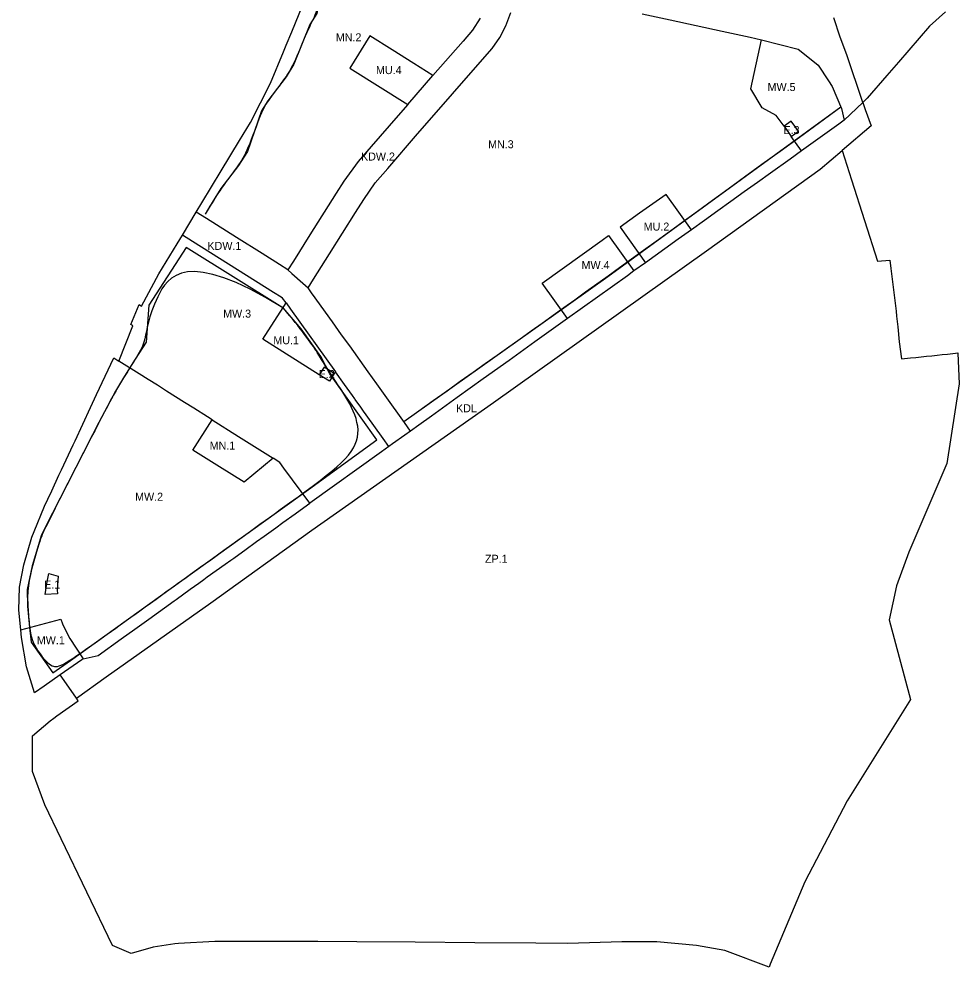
# Model space of a CAD drawing. Extents: x 7421649 to 7422798, y 5542040 to 5543137.
# Drawn here: x 7421743 to 7422272, y 5542040 to 5542573 of the extents above; entities that cross this region are included whole.
import ezdxf

# ---------------------------------------------------------------- set-up
doc = ezdxf.new("R2010")
doc.units = 0
for name, color, linetype in [('linie_rozgraniczajace', 7, 'Continuous'), ('linie_zabudowy_nieprzekraczalne', 7, 'Continuous'), ('oznaczenia_przeznaczen', 7, 'Continuous')]:
    doc.layers.add(name, color=color, linetype=linetype)

msp = doc.modelspace()

# ---------------------------------------------------------------- linework, layer by layer
at = {"layer": 'linie_rozgraniczajace'}
for p, q in [((7421896.4, 5542565.61), (7421904.65, 5542585.63)), ((7422016.73, 5542568.81), (7422019.53, 5542576.39)), ((7422093.43, 5542575.67), (7422109.11, 5542572.26)), ((7422263.95, 5542576.81), (7422254.88, 5542568.62)), ((7422002.25, 5542573.28), (7421997.98, 5542566.51)), ((7422013.26, 5542562.28), (7422016.73, 5542568.81)), ((7422109.11, 5542572.26), (7422123.76, 5542569.07)), ((7422123.76, 5542569.07), (7422138.4, 5542565.87)), ((7422204.6, 5542562.53), (7422201.15, 5542573.32)), ((7421893.27, 5542558.01), (7421896.4, 5542565.61)), ((7421997.98, 5542566.51), (7421992.72, 5542560.37)), ((7422138.4, 5542565.87), (7422154.08, 5542562.47)), ((7422254.88, 5542568.62), (7422237.48, 5542548.49)), ((7421940.34, 5542563.19), (7421928.98, 5542545.12)), ((7421952.79, 5542555.37), (7421940.34, 5542563.19)), ((7421992.72, 5542560.37), (7421975.77, 5542540.92)), ((7422008.97, 5542556.24), (7422013.26, 5542562.28)), ((7422154.08, 5542562.47), (7422160.44, 5542561.08)), ((7422154.45, 5542533.49), (7422160.44, 5542561.08)), ((7422160.44, 5542561.08), (7422181.03, 5542555.82)), ((7422208.35, 5542552.69), (7422204.6, 5542562.53)), ((7421884.37, 5542536.75), (7421891.76, 5542554.35)), ((7421891.76, 5542554.35), (7421893.27, 5542558.01)), ((7421965.02, 5542547.68), (7421952.79, 5542555.37)), ((7422003.6, 5542550.01), (7422008.97, 5542556.24)), ((7422181.03, 5542555.82), (7422188.38, 5542550.04)), ((7421975.77, 5542540.92), (7421965.02, 5542547.68)), ((7421986.73, 5542530.65), (7422003.6, 5542550.01)), ((7422188.38, 5542550.04), (7422192.4, 5542546.88)), ((7422217.47, 5542525.82), (7422208.35, 5542552.69)), ((7422237.48, 5542548.49), (7422230.94, 5542540.92)), ((7421928.98, 5542545.12), (7421961.58, 5542524.63)), ((7422192.4, 5542546.88), (7422198.16, 5542537.92)), ((7421961.58, 5542524.63), (7421975.77, 5542540.92)), ((7422198.16, 5542537.92), (7422200.12, 5542534.87)), ((7422230.94, 5542540.92), (7422219.96, 5542528.19)), ((7421873.19, 5542514.65), (7421884.37, 5542536.75)), ((7422160.86, 5542522.75), (7422154.45, 5542533.49)), ((7422200.12, 5542534.87), (7422205.51, 5542522.37)), ((7421972.53, 5542514.38), (7421986.73, 5542530.65)), ((7422219.96, 5542528.19), (7422217.47, 5542525.82)), ((7421961.58, 5542524.63), (7421956.26, 5542518.53)), ((7422168.78, 5542518.58), (7422160.86, 5542522.75)), ((7422205.51, 5542522.37), (7422207.02, 5542515.84)), ((7422217.47, 5542525.82), (7422207.02, 5542515.84)), ((7422217.47, 5542525.82), (7422218.27, 5542523.48)), ((7422218.27, 5542523.48), (7422218.77, 5542521.9)), ((7422218.77, 5542521.9), (7422222.04, 5542512.78)), ((7421956.26, 5542518.53), (7421941.06, 5542501.06)), ((7422173.15, 5542512.48), (7422168.78, 5542518.58)), ((7422207.02, 5542515.84), (7422203.97, 5542513.66)), ((7421869.03, 5542507.75), (7421873.19, 5542514.65)), ((7421967.13, 5542508.17), (7421972.53, 5542514.38)), ((7422177.21, 5542515.39), (7422173.15, 5542512.48)), ((7422173.15, 5542512.48), (7422177.22, 5542506.79)), ((7422181.29, 5542509.7), (7422177.21, 5542515.39)), ((7422203.97, 5542513.66), (7422183.04, 5542498.66)), ((7422222.04, 5542512.78), (7422205.75, 5542498.85)), ((7421866.99, 5542504.37), (7421869.03, 5542507.75)), ((7421950.29, 5542488.69), (7421967.13, 5542508.17)), ((7422177.22, 5542506.79), (7422181.29, 5542509.7)), ((7422183.04, 5542498.66), (7422177.22, 5542506.79)), ((7421856.74, 5542487.42), (7421866.99, 5542504.37)), ((7421941.06, 5542501.06), (7421933.67, 5542492.56)), ((7422183.04, 5542498.66), (7422176.54, 5542494)), ((7422193.42, 5542488.31), (7422205.75, 5542498.85)), ((7422205.75, 5542498.85), (7422211, 5542482.38)), ((7421933.67, 5542492.56), (7421925.67, 5542481.65)), ((7422176.54, 5542494), (7422165.58, 5542486.15)), ((7421845.84, 5542469.4), (7421856.74, 5542487.42)), ((7421943.29, 5542480.6), (7421950.29, 5542488.69)), ((7422129.51, 5542442.53), (7422193.42, 5542488.31)), ((7422165.58, 5542486.15), (7422158.16, 5542480.84)), ((7421925.67, 5542481.65), (7421921.39, 5542474.89)), ((7421936.89, 5542471.35), (7421943.29, 5542480.6)), ((7422158.16, 5542480.84), (7422150.74, 5542475.52)), ((7422211, 5542482.38), (7422225.61, 5542436.56)), ((7421921.39, 5542474.89), (7421906.57, 5542451.43)), ((7422106.78, 5542474.18), (7422099.36, 5542468.86)), ((7422121.05, 5542454.26), (7422106.78, 5542474.18)), ((7422150.74, 5542475.52), (7422143.31, 5542470.21)), ((7421842.66, 5542464.14), (7421845.84, 5542469.4)), ((7421932.28, 5542464.04), (7421936.89, 5542471.35)), ((7422099.36, 5542468.86), (7422091.93, 5542463.55)), ((7422143.31, 5542470.21), (7422135.89, 5542464.89)), ((7421834.91, 5542451.3), (7421842.66, 5542464.14)), ((7421848.4, 5542460.53), (7421842.66, 5542464.14)), ((7421917.62, 5542440.85), (7421932.28, 5542464.04)), ((7422091.93, 5542463.55), (7422080.98, 5542455.7)), ((7422135.89, 5542464.89), (7422128.47, 5542459.58)), ((7421853.97, 5542457.03), (7421848.4, 5542460.53)), ((7421865.27, 5542449.92), (7421853.97, 5542457.03)), ((7422128.47, 5542459.58), (7422121.05, 5542454.26)), ((7422080.98, 5542455.7), (7422095.24, 5542435.78)), ((7422121.05, 5542454.26), (7422113.62, 5542448.95)), ((7421821.7, 5542429.48), (7421831.92, 5542446.35)), ((7421831.92, 5542446.35), (7421834.91, 5542451.3)), ((7421840.54, 5542447.76), (7421834.91, 5542451.3)), ((7421886.12, 5542419.11), (7421840.54, 5542447.76)), ((7421879.66, 5542440.88), (7421865.27, 5542449.92)), ((7421906.57, 5542451.43), (7421897.26, 5542436.71)), ((7422037.07, 5542424.26), (7422070.93, 5542448.5)), ((7422070.93, 5542448.5), (7422074.47, 5542451.04)), ((7422074.47, 5542451.04), (7422088.73, 5542431.12)), ((7422113.62, 5542448.95), (7422106.2, 5542443.63)), ((7421889.5, 5542434.7), (7421879.66, 5542440.88)), ((7422009.88, 5542357.13), (7422129.51, 5542442.53)), ((7422106.2, 5542443.63), (7422095.24, 5542435.78)), ((7421897.26, 5542436.71), (7421894.14, 5542431.78)), ((7421908.56, 5542426.52), (7421917.62, 5542440.85)), ((7422095.24, 5542435.78), (7422088.73, 5542431.12)), ((7422225.61, 5542436.56), (7422232.58, 5542437.19)), ((7422232.58, 5542437.19), (7422233.27, 5542432.57)), ((7421894.14, 5542431.78), (7421889.5, 5542434.7)), ((7421894.14, 5542431.78), (7421896.39, 5542429.79)), ((7422088.73, 5542431.12), (7422085.05, 5542428.48)), ((7422233.27, 5542432.57), (7422233.63, 5542429.57)), ((7421811.94, 5542411.41), (7421821.7, 5542429.48)), ((7421896.39, 5542429.79), (7421902.63, 5542424.27)), ((7421905.52, 5542421.72), (7421908.56, 5542426.52)), ((7422085.05, 5542428.48), (7422051.34, 5542404.34)), ((7422233.63, 5542429.57), (7422233.98, 5542426.57)), ((7422233.98, 5542426.57), (7422234.33, 5542423.58)), ((7421902.63, 5542424.27), (7421905.52, 5542421.72)), ((7421907.91, 5542418.38), (7421905.52, 5542421.72)), ((7422051.34, 5542404.34), (7422037.07, 5542424.26)), ((7422234.33, 5542423.58), (7422234.68, 5542420.59)), ((7422234.68, 5542420.59), (7422235.03, 5542417.6)), ((7421890.42, 5542416.4), (7421886.12, 5542419.11)), ((7421891.25, 5542415.88), (7421890.42, 5542416.4)), ((7421893.15, 5542413.23), (7421891.25, 5542415.88)), ((7421908.09, 5542418.13), (7421907.91, 5542418.38)), ((7421919.29, 5542402.49), (7421908.09, 5542418.13)), ((7422235.03, 5542417.6), (7422235.38, 5542414.61)), ((7422235.38, 5542414.61), (7422235.74, 5542411.62)), ((7421805.81, 5542401.09), (7421810.65, 5542412.21)), ((7421810.65, 5542412.21), (7421811.94, 5542411.41)), ((7421880.12, 5542392.76), (7421893.15, 5542413.23)), ((7421893.15, 5542413.23), (7421895.75, 5542409.61)), ((7421895.75, 5542409.61), (7421920.88, 5542374.53)), ((7422235.74, 5542411.62), (7422236.09, 5542408.63)), ((7422051.34, 5542404.34), (7422044.83, 5542399.68)), ((7422236.09, 5542408.63), (7422236.44, 5542405.65)), ((7422236.44, 5542405.65), (7422236.79, 5542402.66)), ((7421799.17, 5542380.46), (7421807.1, 5542400.28)), ((7421807.1, 5542400.28), (7421805.81, 5542401.09)), ((7421924.41, 5542395.34), (7421919.29, 5542402.49)), ((7422044.83, 5542399.68), (7422033.08, 5542391.27)), ((7422236.79, 5542402.66), (7422237.14, 5542399.67)), ((7422237.14, 5542399.67), (7422237.89, 5542391.37)), ((7421928.95, 5542388.99), (7421924.41, 5542395.34)), ((7421911.86, 5542372.8), (7421880.12, 5542392.76)), ((7421939.38, 5542374.42), (7421928.95, 5542388.99)), ((7422033.08, 5542391.27), (7422018.54, 5542380.85)), ((7422237.89, 5542391.37), (7422239.16, 5542381.72)), ((7421786.63, 5542361.7), (7421796.27, 5542382.28)), ((7421796.27, 5542382.28), (7421799.17, 5542380.46)), ((7422244.19, 5542382.24), (7422247.18, 5542382.56)), ((7422247.18, 5542382.56), (7422250.17, 5542382.87)), ((7422250.17, 5542382.87), (7422253.16, 5542383.19)), ((7422253.16, 5542383.19), (7422256.15, 5542383.51)), ((7422256.15, 5542383.51), (7422259.14, 5542383.82)), ((7422259.14, 5542383.82), (7422262.13, 5542384.13)), ((7422262.13, 5542384.13), (7422265.12, 5542384.45)), ((7422265.12, 5542384.45), (7422268.11, 5542384.76)), ((7422268.11, 5542384.76), (7422271.1, 5542385.07)), ((7422271.1, 5542385.07), (7422270.83, 5542384.9)), ((7422270.83, 5542384.9), (7422271.53, 5542367.62)), ((7421810.5, 5542373.33), (7421799.17, 5542380.46)), ((7421914.58, 5542377.13), (7421911.86, 5542372.8)), ((7421920.25, 5542373.56), (7421914.58, 5542377.13)), ((7422018.54, 5542380.85), (7422003.98, 5542370.43)), ((7422239.16, 5542381.72), (7422244.19, 5542382.24)), ((7421815.65, 5542370.1), (7421810.5, 5542373.33)), ((7421917.54, 5542369.24), (7421911.86, 5542372.8)), ((7421920.25, 5542373.56), (7421917.54, 5542369.24)), ((7421920.88, 5542374.53), (7421920.25, 5542373.56)), ((7421926.01, 5542367.38), (7421920.88, 5542374.53)), ((7421944.12, 5542367.78), (7421939.38, 5542374.42)), ((7421820.81, 5542366.87), (7421815.65, 5542370.1)), ((7421825.88, 5542363.66), (7421820.81, 5542366.87)), ((7421930.53, 5542361.07), (7421926.01, 5542367.38)), ((7421944.24, 5542367.62), (7421944.12, 5542367.78)), ((7421948.9, 5542361.12), (7421944.24, 5542367.62)), ((7422003.98, 5542370.43), (7421989.43, 5542360)), ((7422271.53, 5542367.62), (7422264.64, 5542322.9)), ((7421783.24, 5542354.35), (7421786.63, 5542361.7)), ((7421830.96, 5542360.46), (7421825.88, 5542363.66)), ((7421931.75, 5542359.34), (7421930.53, 5542361.07)), ((7421959.75, 5542345.97), (7421948.9, 5542361.12)), ((7421836.11, 5542357.23), (7421830.96, 5542360.46)), ((7421841.27, 5542354), (7421836.11, 5542357.23)), ((7421907.61, 5542285.51), (7422009.88, 5542357.13)), ((7421932.06, 5542358.89), (7421931.75, 5542359.34)), ((7421935.11, 5542354.64), (7421932.06, 5542358.89)), ((7421989.43, 5542360), (7421974.88, 5542349.58)), ((7421774.58, 5542335.75), (7421783.24, 5542354.35)), ((7421848.99, 5542349.14), (7421841.27, 5542354)), ((7421935.58, 5542353.98), (7421935.11, 5542354.64)), ((7421936.72, 5542352.39), (7421935.58, 5542353.98)), ((7421938.17, 5542350.36), (7421936.72, 5542352.39)), ((7421947.68, 5542337.08), (7421938.17, 5542350.36)), ((7421840.79, 5542330.47), (7421851.53, 5542347.54)), ((7421851.53, 5542347.54), (7421848.99, 5542349.14)), ((7421851.53, 5542347.54), (7421866.37, 5542338.2)), ((7421963.17, 5542341.2), (7421959.75, 5542345.97)), ((7421974.88, 5542349.58), (7421967.79, 5542344.51)), ((7421963.17, 5542341.2), (7421959.94, 5542338.89)), ((7421967.79, 5542344.51), (7421963.17, 5542341.2)), ((7421773.52, 5542333.5), (7421774.58, 5542335.75)), ((7421866.37, 5542338.2), (7421885.97, 5542325.89)), ((7421950.98, 5542332.47), (7421947.68, 5542337.08)), ((7421959.94, 5542338.89), (7421953.02, 5542333.93)), ((7421766.83, 5542319.3), (7421773.52, 5542333.5)), ((7421855.74, 5542321.09), (7421840.79, 5542330.47)), ((7421946.73, 5542329.42), (7421906.51, 5542300.62)), ((7421950.98, 5542332.47), (7421946.73, 5542329.42)), ((7421953.02, 5542333.93), (7421950.98, 5542332.47)), ((7421885.97, 5542325.89), (7421869.53, 5542312.42)), ((7421889.63, 5542323.58), (7421885.97, 5542325.89)), ((7421765.42, 5542316.31), (7421766.83, 5542319.3)), ((7421869.53, 5542312.42), (7421855.74, 5542321.09)), ((7421892, 5542320.36), (7421889.63, 5542323.58)), ((7421906.51, 5542300.62), (7421892, 5542320.36)), ((7422264.64, 5542322.9), (7422243.24, 5542273.2)), ((7421761.42, 5542307.66), (7421765.42, 5542316.31)), ((7421759.15, 5542302.83), (7421761.42, 5542307.66)), ((7421757.37, 5542299.03), (7421759.15, 5542302.83)), ((7421751.47, 5542284.76), (7421757.37, 5542299.03)), ((7421899.07, 5542295.23), (7421906.51, 5542300.62)), ((7421891.41, 5542289.72), (7421898.36, 5542294.72)), ((7421898.36, 5542294.72), (7421899.07, 5542295.23)), ((7421880.87, 5542282.15), (7421887.36, 5542286.8)), ((7421887.36, 5542286.8), (7421891.41, 5542289.72)), ((7421745.65, 5542266.01), (7421750.26, 5542281.54)), ((7421750.26, 5542281.54), (7421751.47, 5542284.76)), ((7421850.94, 5542244.63), (7421907.61, 5542285.51)), ((7421876.57, 5542279.03), (7421880.87, 5542282.15)), ((7421869.94, 5542274.25), (7421876.57, 5542279.03)), ((7421863.71, 5542269.8), (7421868.59, 5542273.28)), ((7421868.59, 5542273.28), (7421869.94, 5542274.25)), ((7422243.24, 5542273.2), (7422236.4, 5542254.21)), ((7421743.28, 5542253.48), (7421745.65, 5542266.01)), ((7421853.89, 5542262.76), (7421858.84, 5542266.3)), ((7421858.84, 5542266.3), (7421862.14, 5542268.68)), ((7421862.14, 5542268.68), (7421863.71, 5542269.8)), ((7421758.58, 5542255.52), (7421759.73, 5542261.19)), ((7421759.73, 5542261.19), (7421765.11, 5542259.71)), ((7421765.11, 5542259.71), (7421764.44, 5542251.98)), ((7421848.9, 5542259.25), (7421853.89, 5542262.76)), ((7421757.8, 5542249.25), (7421758.58, 5542255.52)), ((7421839.18, 5542252.23), (7421844.07, 5542255.73)), ((7421844.07, 5542255.73), (7421846.85, 5542257.73)), ((7421846.85, 5542257.73), (7421848.9, 5542259.25)), ((7421742.99, 5542240.51), (7421743.28, 5542253.48)), ((7421764.59, 5542249.76), (7421757.8, 5542249.25)), ((7421764.44, 5542251.98), (7421764.59, 5542249.76)), ((7421831.42, 5542246.45), (7421839.18, 5542252.23)), ((7422236.4, 5542254.21), (7422232.28, 5542235.02)), ((7421792.01, 5542202.97), (7421850.94, 5542244.63)), ((7421815.95, 5542235.44), (7421830.17, 5542245.71)), ((7421830.17, 5542245.71), (7421831.42, 5542246.45)), ((7421743.96, 5542229.39), (7421742.99, 5542240.51)), ((7421743.97, 5542229.39), (7421766.46, 5542235.55)), ((7421766.46, 5542235.55), (7421767.41, 5542232.81)), ((7421808.23, 5542229.87), (7421815.95, 5542235.44)), ((7422232.28, 5542235.02), (7422244.2, 5542190.37)), ((7421743.96, 5542229.39), (7421743.97, 5542229.39)), ((7421744.34, 5542225.11), (7421743.96, 5542229.39)), ((7421767.41, 5542232.81), (7421769.55, 5542228.56)), ((7421769.55, 5542228.56), (7421771.58, 5542224.51)), ((7421800.53, 5542224.38), (7421808.23, 5542229.87)), ((7421747.25, 5542208.61), (7421744.34, 5542225.11)), ((7421771.58, 5542224.51), (7421779.16, 5542213.26)), ((7421787.54, 5542215), (7421800.53, 5542224.38)), ((7421778.34, 5542212.69), (7421766.2, 5542204.16)), ((7421779.16, 5542213.26), (7421778.34, 5542212.69)), ((7421779.16, 5542213.26), (7421787.54, 5542215)), ((7421751.78, 5542194.03), (7421747.25, 5542208.61)), ((7421766.2, 5542204.16), (7421757.09, 5542197.76)), ((7421769.64, 5542199.21), (7421766.2, 5542204.16)), ((7421775.42, 5542191.11), (7421792.01, 5542202.97)), ((7421757.09, 5542197.76), (7421751.78, 5542194.03)), ((7421775.42, 5542191.11), (7421769.64, 5542199.21)), ((7421776.37, 5542189.64), (7421775.42, 5542191.11)), ((7421764.37, 5542181.11), (7421776.37, 5542189.64)), ((7422244.2, 5542190.37), (7422208.58, 5542133.38)), ((7421762.58, 5542179.77), (7421764.37, 5542181.11)), ((7421750.7, 5542169.92), (7421760.62, 5542178.29)), ((7421760.62, 5542178.29), (7421762.58, 5542179.77)), ((7421750.64, 5542149.78), (7421750.7, 5542169.92)), ((7421757.48, 5542131.19), (7421750.64, 5542149.78)), ((7422208.58, 5542133.38), (7422184.81, 5542087.89)), ((7421766.71, 5542112), (7421757.48, 5542131.19)), ((7421795.53, 5542052.08), (7421766.71, 5542112)), ((7422184.81, 5542087.89), (7422165.39, 5542041.6)), ((7421806.12, 5542047.6), (7421795.53, 5542052.08)), ((7421830.54, 5542052.92), (7421818.45, 5542051.07)), ((7421832.72, 5542053.25), (7421830.54, 5542052.92)), ((7421853.03, 5542054.41), (7421832.72, 5542053.25)), ((7421868.97, 5542054.37), (7421853.03, 5542054.41)), ((7421910.99, 5542054.27), (7421868.97, 5542054.37)), ((7421932.98, 5542054.07), (7421910.99, 5542054.27)), ((7421965.79, 5542053.86), (7421932.98, 5542054.07)), ((7421999.28, 5542053.59), (7421965.79, 5542053.86)), ((7422033.6, 5542053.38), (7421999.28, 5542053.59)), ((7422051.6, 5542053.26), (7422033.6, 5542053.38)), ((7422081.89, 5542054.06), (7422051.6, 5542053.26)), ((7422101.56, 5542054.13), (7422081.89, 5542054.06)), ((7422123.9, 5542052), (7422101.56, 5542054.13)), ((7422139.91, 5542049.18), (7422123.9, 5542052)), ((7421818.45, 5542051.07), (7421806.12, 5542047.6)), ((7422164.7, 5542039.97), (7422139.91, 5542049.18)), ((7422165.39, 5542041.6), (7422164.7, 5542039.97))]:
    msp.add_line(p, q, dxfattribs=at)
at = {"layer": 'linie_zabudowy_nieprzekraczalne'}
for points in [[(7421931.3, 5542635.53), (7421928.2, 5542630.6), (7421923.97, 5542622.32), (7421918.73, 5542599.97), (7421913.78, 5542592.09), (7421910.39, 5542575.81), (7421906.57, 5542569.72), (7421897.62, 5542547.34), (7421893.26, 5542540.3), (7421882.95, 5542526.81), (7421879.44, 5542521.22), (7421871.4, 5542498.34), (7421866.41, 5542490.4), (7421856.51, 5542477.52), (7421851.56, 5542469.65), (7421847.6, 5542463.03)], [(7421959.29, 5542346.61), (7422052.02, 5542412.27), (7422074.06, 5542427.96), (7422205.08, 5542523.36)], [(7421891.3, 5542410.42), (7421836.93, 5542444.37), (7421816.1, 5542411.89), (7421814.46, 5542391.14), (7421808.42, 5542381.55), (7421802.34, 5542371.97), (7421797.19, 5542363.61), (7421787.85, 5542346.01), (7421757.62, 5542286.51), (7421755.75, 5542282.9), (7421750.35, 5542265.34), (7421747.66, 5542252.12), (7421747.88, 5542242.71), (7421748.97, 5542230.76), (7421749.86, 5542222.59), (7421761.99, 5542205.21), (7421772.03, 5542212.24), (7421905.84, 5542308.38), (7421944.14, 5542336.26), (7421917.72, 5542373.24), (7421912.62, 5542383.06), (7421901.68, 5542398.53), (7421891.49, 5542410.42)]]:
    msp.add_lwpolyline(points, dxfattribs=at)
for points in [[(7421931.3, 5542635.53), (7421928.2, 5542630.6), (7421923.97, 5542622.32), (7421918.73, 5542599.97), (7421913.78, 5542592.09), (7421910.39, 5542575.81), (7421906.57, 5542569.72), (7421897.62, 5542547.34), (7421893.26, 5542540.3), (7421882.95, 5542526.81), (7421879.44, 5542521.22), (7421871.4, 5542498.34), (7421866.41, 5542490.4), (7421856.51, 5542477.52), (7421851.56, 5542469.65), (7421847.6, 5542463.03)], [(7421959.29, 5542346.61), (7422052.02, 5542412.27), (7422074.06, 5542427.96), (7422205.08, 5542523.36)], [(7421891.3, 5542410.42), (7421836.93, 5542444.37), (7421816.1, 5542411.89), (7421814.46, 5542391.14), (7421808.42, 5542381.55), (7421802.34, 5542371.97), (7421797.19, 5542363.61), (7421787.85, 5542346.01), (7421757.62, 5542286.51), (7421755.75, 5542282.9), (7421750.35, 5542265.34), (7421747.66, 5542252.12), (7421747.88, 5542242.71), (7421748.97, 5542230.76), (7421749.86, 5542222.59), (7421761.99, 5542205.21), (7421772.03, 5542212.24), (7421905.84, 5542308.38), (7421944.14, 5542336.26), (7421917.72, 5542373.24), (7421912.62, 5542383.06), (7421901.68, 5542398.53), (7421891.49, 5542410.42)]]:
    msp.add_open_spline(points, degree=3, dxfattribs=at)

# ---------------------------------------------------------------- texts
at = {"layer": 'oznaczenia_przeznaczen'}
for s, p in [('MN.2', (7421921.14, 5542560.19)), ('MU.4', (7421943.74, 5542541.78)), ('MW.5', (7422163.9, 5542532.27)), ('E.3', (7422172.83, 5542508.07)), ('MN.3', (7422006.75, 5542500.1)), ('KDW.2', (7421935.3, 5542493.19)), ('MU.2', (7422094.23, 5542453.84)), ('KDW.1', (7421848.97, 5542442.99)), ('MW.4', (7422059.29, 5542432.18)), ('MW.3', (7421857.79, 5542404.93)), ('MU.1', (7421886.02, 5542389.97)), ('E.2', (7421911.51, 5542370.94)), ('KDL', (7421988.75, 5542351.73)), ('MN.1', (7421850.21, 5542330.76)), ('MW.2', (7421808.3, 5542302.01)), ('ZP.1', (7422005.02, 5542267.16)), ('E.1', (7421757.15, 5542252.66)), ('MW.1', (7421753.04, 5542221.39))]:
    msp.add_text(s, height=4.5, dxfattribs=at).set_placement(p)

doc.saveas('drawing.dxf')
